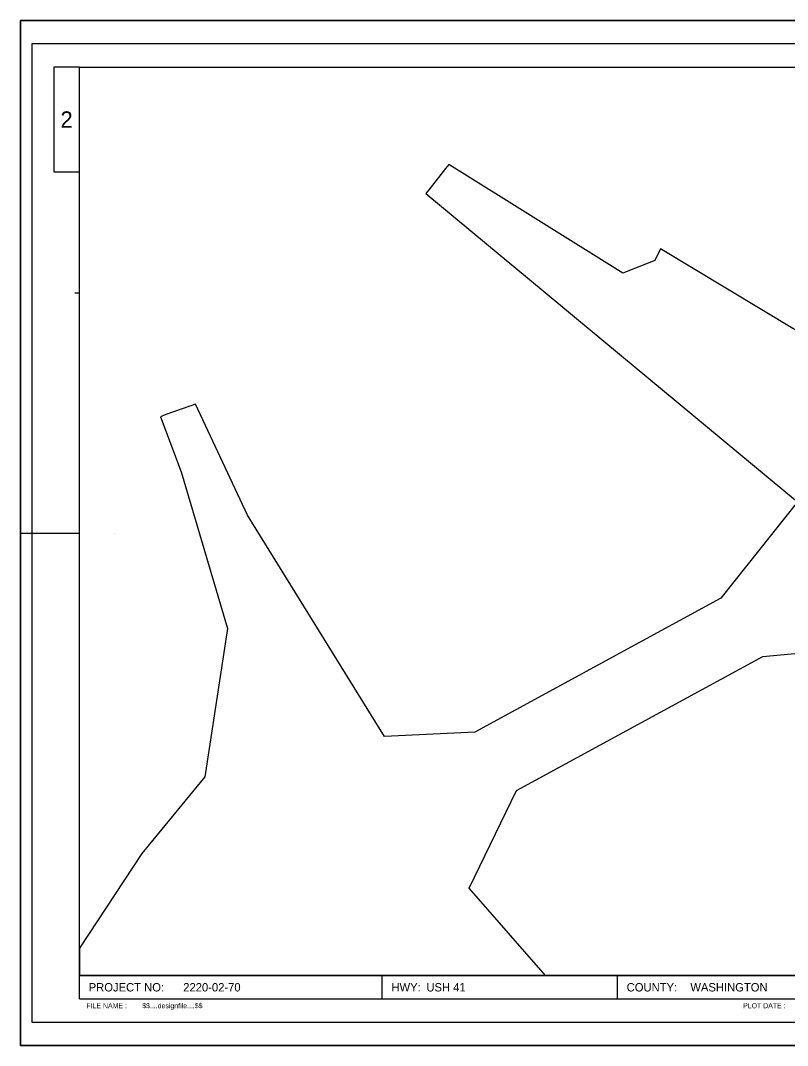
# Model space of a CAD drawing. Extents: x 358553 to 360253, y 132337 to 133437.
# Drawn here: x 358553 to 359376, y 132337 to 133437 of the extents above; entities that cross this region are included whole.
import ezdxf

# ---------------------------------------------------------------- set-up
doc = ezdxf.new("R2010")
doc.units = 0
for name, color, linetype in [('Default', 7, 'Continuous'), ('P_ALI_200_PIData', 7, 'Continuous'), ('P_ALI_200_Sta', 7, 'Continuous'), ('P_ALI_200_Tic', 7, 'Continuous'), ('P_ALI_50_Equation', 7, 'Continuous')]:
    doc.layers.add(name, color=color, linetype=linetype)

msp = doc.modelspace()

# ---------------------------------------------------------------- linework, layer by layer
at = {"layer": 'Default'}
msp.add_lwpolyline([(360190.8, 132411.9), (358615.8, 132411.9), (358615.8, 133386.9), (359975.4, 133386.9), (360190.8, 132978.3)], close=True, dxfattribs=at)
for points in [[(359764, 132411.9), (358615.8, 132411.9), (358615.8, 133386.9), (359975.4, 133386.9)], [(359420.2, 133083.1), (359239.6, 133191.8), (359233.4, 133179.2), (359199.3, 133165.6), (359012.3, 133282.5), (359008.9, 133278.2), (358992.3, 133256.9), (358987.8, 133251.2), (359386.6, 132920.5), (359304.4, 132816.8), (359040.2, 132673.3), (358943.3, 132668.7), (358796.3, 132906), (358740.4, 133025.2), (358734.2, 133023.2), (358708.7, 133014.1), (358702.7, 133011.7), (358725.2, 132952.6), (358774.8, 132784.5), (358750.3, 132625.4), (358682.7, 132542.8), (358615.8, 132441.4), (358615.8, 132411.9), (359116.3, 132411.9), (359034.1, 132505.8), (359085, 132610.6), (359349.3, 132754.2), (359478.5, 132766.7)]]:
    msp.add_lwpolyline(points, dxfattribs=at)
at = {"layer": 'P_ALI_200_PIData'}
for points in [[(358552.6, 132336.9), (360252.6, 132336.9), (360252.6, 133436.9), (358552.6, 133436.9)], [(358564.6, 132361.9), (360219.6, 132361.9), (360219.6, 133411.9), (358564.6, 133411.9)]]:
    msp.add_lwpolyline(points, close=True, dxfattribs=at)
at = {"layer": 'P_ALI_200_Sta'}
for p, q in [((358552.6, 133386.9), (358552.6, 133436.9)), ((358552.6, 133436.9), (358602.6, 133436.9)), ((358615.8, 133386.9), (360190.8, 133386.9)), ((358615.8, 132386.9), (358615.8, 133386.9)), ((358615.8, 133144.4), (358610.8, 133144.4)), ((358552.6, 132861.9), (358552.6, 132911.9)), ((358552.6, 132886.9), (358615.8, 132886.9)), ((358653.3, 132886.9), (358653.3, 132886.9)), ((358615.8, 132411.9), (360190.8, 132411.9)), ((358940.8, 132386.9), (358940.8, 132411.9)), ((359193.3, 132386.9), (359193.3, 132411.9)), ((358552.6, 132336.9), (358552.6, 132386.9)), ((358615.8, 132386.9), (360190.8, 132386.9)), ((358552.6, 132336.9), (358602.6, 132336.9))]:
    msp.add_line(p, q, dxfattribs=at)
msp.add_lwpolyline([(358615.8, 133386.9), (358588.3, 133386.9), (358588.3, 133274.4), (358615.8, 133274.4)], close=True, dxfattribs=at)
at = {"layer": 'P_ALI_200_Tic'}
msp.add_lwpolyline([(358552.6, 133436.9), (360252.6, 133436.9), (360252.6, 132336.9), (358552.6, 132336.9), (358552.6, 133436.9)], dxfattribs=at)
at = {"layer": 'P_ALI_50_Equation'}
msp.add_lwpolyline([(358552.6, 133436.9), (360252.6, 133436.9), (360252.6, 132336.9), (358552.6, 132336.9)], close=True, dxfattribs=at)

# ---------------------------------------------------------------- texts
at = {"layer": 'P_ALI_200_Sta'}
for s, height, p in [('2', 17.5, (358595.5, 133321.9)), ('PROJECT NO:', 9, (358625.8, 132394.9)), ('2220-02-70 ', 9, (358727.3, 132394.9)), ('HWY:', 9, (358950.8, 132394.9)), ('USH 41', 9, (358988.3, 132394.9)), ('COUNTY:', 9, (359203.3, 132394.9)), (' WASHINGTON', 9, (359268.3, 132394.9)), ('FILE NAME :', 5.4, (358623.3, 132376.9))]:
    msp.add_text(s, height=height, dxfattribs=at).set_placement(p)
for s, p in [('$$....designfile....$$', (358683.3, 132376.9)), ('PLOT DATE :', (359328.3, 132376.9))]:
    msp.add_text(s, height=5.4, rotation=360, dxfattribs=at).set_placement(p)

doc.saveas('drawing.dxf')
